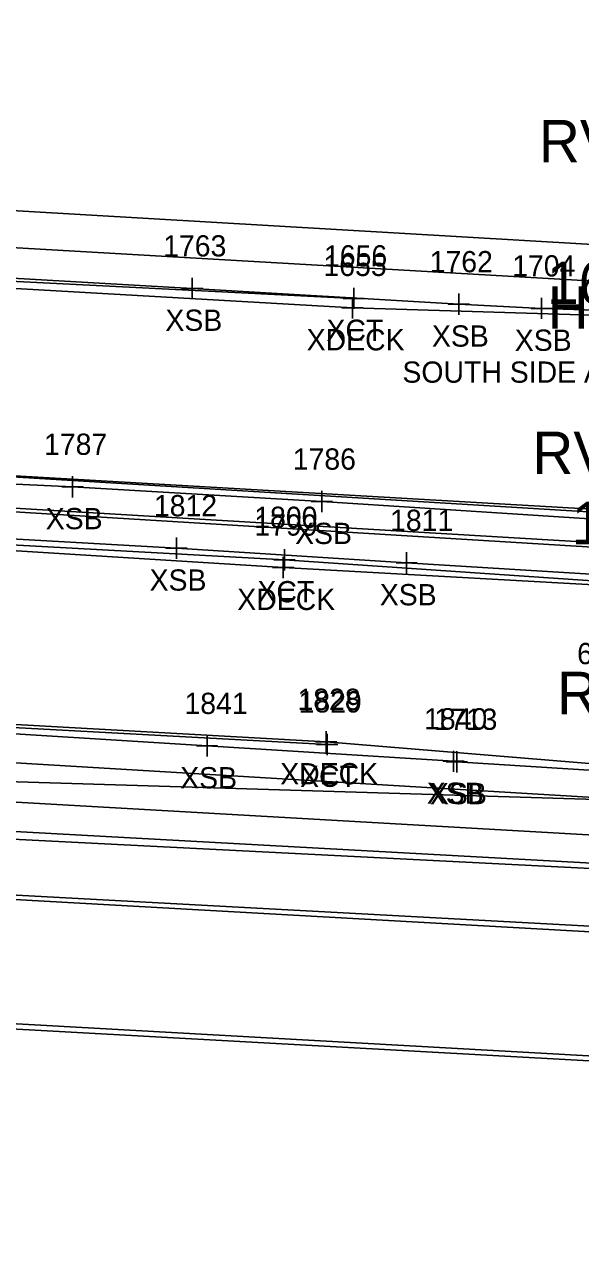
# Model space of a CAD drawing. Extents: x 1461855 to 1464118, y 556196 to 557441.
# Drawn here: x 1462290.7 to 1462316.9, y 556394.7 to 556452.7 of the extents above; entities that cross this region are included whole.
import ezdxf

# ---------------------------------------------------------------- set-up
doc = ezdxf.new("R2010")
doc.units = 0
for name, color, linetype in [('B_A', 7, 'Continuous'), ('B_C', 7, 'Continuous'), ('B_I', 7, 'Continuous'), ('B_TIC', 7, 'Continuous'), ('BB', 7, 'Continuous'), ('BDC', 7, 'Continuous'), ('BDEFAULT', 7, 'Continuous'), ('BELB', 7, 'Continuous'), ('BR', 7, 'Continuous'), ('C_A', 7, 'Continuous'), ('L_A', 7, 'Continuous'), ('L_I', 7, 'Continuous'), ('LSOGP', 7, 'Continuous'), ('UW', 7, 'Continuous')]:
    doc.layers.add(name, color=color, linetype=linetype)

msp = doc.modelspace()

# ---------------------------------------------------------------- linework, layer by layer
at = {"layer": 'B_TIC'}
for p, q in [((1462298.615, 556440.288), (1462298.691, 556440.288)), ((1462306.16, 556439.369), (1462306.236, 556439.369)), ((1462306.214, 556439.817), (1462306.289, 556439.817)), ((1462311.16, 556439.545), (1462311.236, 556439.545)), ((1462315.06, 556439.347), (1462315.135, 556439.347)), ((1462292.986, 556430.953), (1462293.061, 556430.953)), ((1462304.72, 556430.256), (1462304.795, 556430.256)), ((1462297.873, 556428.062), (1462297.949, 556428.062)), ((1462302.891, 556427.151), (1462302.967, 556427.151)), ((1462302.964, 556427.514), (1462303.039, 556427.514)), ((1462308.706, 556427.372), (1462308.782, 556427.372)), ((1462299.313, 556418.758), (1462299.388, 556418.758)), ((1462304.914, 556418.948), (1462304.989, 556418.948)), ((1462304.97, 556418.828), (1462305.046, 556418.828)), ((1462310.916, 556418.032), (1462310.992, 556418.032)), ((1462311.066, 556418.012), (1462311.141, 556418.012))]:
    msp.add_line(p, q, dxfattribs=at)
for points in [[(1462298.612, 556439.788), (1462298.612, 556440.788)], [(1462298.112, 556440.288), (1462299.112, 556440.288)], [(1462306.157, 556438.869), (1462306.157, 556439.869)], [(1462306.21, 556439.317), (1462306.21, 556440.317)], [(1462311.157, 556439.045), (1462311.157, 556440.045)], [(1462305.657, 556439.369), (1462306.657, 556439.369)], [(1462305.71, 556439.817), (1462306.71, 556439.817)], [(1462310.657, 556439.545), (1462311.657, 556439.545)], [(1462314.556, 556439.347), (1462315.556, 556439.347)], [(1462315.056, 556438.847), (1462315.056, 556439.847)], [(1462292.982, 556430.453), (1462292.982, 556431.453)], [(1462292.482, 556430.953), (1462293.482, 556430.953)], [(1462304.716, 556429.756), (1462304.716, 556430.756)], [(1462304.216, 556430.256), (1462305.216, 556430.256)], [(1462297.87, 556427.562), (1462297.87, 556428.562)], [(1462297.37, 556428.062), (1462298.37, 556428.062)], [(1462302.96, 556427.014), (1462302.96, 556428.014)], [(1462308.703, 556426.872), (1462308.703, 556427.872)], [(1462302.388, 556427.151), (1462303.388, 556427.151)], [(1462302.46, 556427.514), (1462303.46, 556427.514)], [(1462302.888, 556426.651), (1462302.888, 556427.651)], [(1462308.203, 556427.372), (1462309.203, 556427.372)], [(1462299.309, 556418.258), (1462299.309, 556419.258)], [(1462304.91, 556418.448), (1462304.91, 556419.448)], [(1462304.967, 556418.328), (1462304.967, 556419.328)], [(1462298.809, 556418.758), (1462299.809, 556418.758)], [(1462304.41, 556418.948), (1462305.41, 556418.948)], [(1462304.467, 556418.828), (1462305.467, 556418.828)], [(1462310.913, 556417.532), (1462310.913, 556418.532)], [(1462311.062, 556417.512), (1462311.062, 556418.512)], [(1462310.413, 556418.032), (1462311.413, 556418.032)], [(1462310.562, 556418.012), (1462311.562, 556418.012)]]:
    msp.add_lwpolyline(points, dxfattribs=at)
at = {"layer": 'BB'}
for points in [[(1462330.314, 556439.882), (1462152.032, 556450.172)], [(1462330.281, 556438.56), (1462322.158, 556439.115), (1462315.056, 556439.347), (1462311.157, 556439.545), (1462298.612, 556440.288), (1462285.489, 556441.028), (1462275.964, 556441.553), (1462262.291, 556442.26), (1462250.561, 556442.934), (1462239.101, 556443.725), (1462221.451, 556445.028), (1462206.294, 556446.009), (1462196.428, 556446.584), (1462185.17, 556447.223), (1462170.563, 556447.948), (1462158.846, 556448.597), (1462153.063, 556449.174)], [(1462328.781, 556428.634), (1462324.065, 556428.892), (1462319.456, 556429.171), (1462319.262, 556429.313), (1462304.716, 556430.256), (1462292.982, 556430.953), (1462284.287, 556431.363), (1462273.947, 556431.84), (1462261.623, 556432.561), (1462248.124, 556433.552), (1462226.107, 556434.532), (1462213.355, 556435.513), (1462200.264, 556436.133), (1462186.601, 556437.408), (1462174.891, 556438.04), (1462163.053, 556438.684), (1462157.864, 556438.972), (1462151.418, 556439.478)], [(1462329.779, 556427.349), (1462151.293, 556438.257)], [(1462328.685, 556426.103), (1462325.057, 556426.385), (1462319.713, 556426.698), (1462318.91, 556426.742), (1462308.703, 556427.372), (1462297.87, 556428.062), (1462287.86, 556428.625), (1462279.228, 556429.453), (1462266.621, 556430.191), (1462257.639, 556430.745), (1462248.392, 556431.143), (1462238.993, 556431.689), (1462230.236, 556432.512), (1462221.1, 556433.4), (1462212.022, 556433.761), (1462203.22, 556433.862), (1462192.615, 556434.352), (1462181.798, 556435.051), (1462171.497, 556435.694), (1462163.387, 556436.205), (1462158.362, 556436.371), (1462151.163, 556436.853)], [(1462329.432, 556416.833), (1462323.508, 556417.23), (1462311.062, 556418.012), (1462310.913, 556418.032), (1462299.309, 556418.758), (1462286.726, 556419.548), (1462277.774, 556420.048), (1462264.748, 556420.883), (1462247.065, 556421.852), (1462234.884, 556422.524), (1462220.758, 556423.428), (1462206.908, 556424.316), (1462197.488, 556424.752), (1462189.82, 556425.214), (1462178.304, 556425.855), (1462168.167, 556426.338), (1462157.727, 556426.705), (1462150.543, 556427.374)], [(1462329.287, 556415.62), (1462150.452, 556426.331)]]:
    msp.add_lwpolyline(points, dxfattribs=at)
at = {"layer": 'BDC'}
for points in [[(1462306.21, 556439.817), (1462267.643, 556441.754), (1462231.479, 556443.795), (1462195.28, 556445.964), (1462174.6, 556447.094)], [(1462330.253, 556427.044), (1462330.307, 556427.885), (1462321.119, 556429.542), (1462284.961, 556431.731), (1462249.264, 556433.812), (1462199.694, 556436.845), (1462158.901, 556439.284), (1462149.578, 556438.742), (1462149.473, 556437.83)], [(1462330.253, 556427.044), (1462320.906, 556426.297), (1462302.96, 556427.514), (1462266.959, 556429.497), (1462221.647, 556432.248), (1462185.847, 556434.519), (1462158.743, 556436.243), (1462149.473, 556437.83)], [(1462304.967, 556418.828), (1462275.389, 556420.423), (1462239.223, 556422.53), (1462203.029, 556424.75), (1462173.597, 556426.538)]]:
    msp.add_lwpolyline(points, dxfattribs=at)
at = {"layer": 'BDEFAULT'}
for points in [[(1462340.791, 556440.982), (1462140.486, 556452.697)], [(1462339.926, 556427), (1462139.852, 556438.871)], [(1462339.234, 556413.311), (1462138.867, 556424.749)], [(1462328.804, 556412.4), (1462155.31, 556421.202)]]:
    msp.add_lwpolyline(points, dxfattribs=at)
at = {"layer": 'BELB'}
for points in [[(1462332.261, 556438.564), (1462306.157, 556439.369), (1462267.585, 556441.59), (1462231.402, 556443.714), (1462195.311, 556445.79), (1462174.59, 556446.765), (1462149.769, 556449.202)], [(1462330.387, 556427.996), (1462321.219, 556429.671), (1462285.084, 556431.77), (1462249.268, 556434.079), (1462199.778, 556436.979), (1462159.012, 556439.444), (1462149.101, 556439.166)], [(1462330.387, 556427.996), (1462330.292, 556426.802), (1462320.892, 556426.149), (1462302.888, 556427.151), (1462266.996, 556429.395), (1462221.723, 556432.192), (1462185.76, 556434.369), (1462158.715, 556435.82), (1462149.068, 556437.555)], [(1462331.212, 556416.788), (1462304.91, 556418.948), (1462275.378, 556420.599), (1462239.194, 556422.631), (1462203.113, 556424.823), (1462173.724, 556426.567), (1462149.901, 556428.267), (1462148.306, 556426.947)], [(1462337.183, 556408.895), (1462260.894, 556413.183), (1462204.489, 556416.212), (1462146.838, 556419.281)], [(1462336.881, 556403.082), (1462260.891, 556407.332), (1462205.408, 556410.17), (1462146.764, 556413.378)]]:
    msp.add_lwpolyline(points, dxfattribs=at)
at = {"layer": 'BR'}
for points in [[(1462338.998, 556414.351), (1462338.8, 556409.121), (1462204.423, 556416.373), (1462146.886, 556419.56), (1462146.979, 556424.973)], [(1462356.157, 556401.791), (1462336.856, 556402.851), (1462260.866, 556407.054), (1462205.402, 556409.871), (1462146.909, 556413.108), (1462126.732, 556414.71), (1462111.281, 556416.663), (1462102.284, 556418.456)]]:
    msp.add_lwpolyline(points, dxfattribs=at)
at = {"layer": 'LSOGP'}
msp.add_lwpolyline([(1462152.286, 556411.553), (1462201.558, 556420.694), (1462202.678, 556419.763), (1462203.798, 556418.832), (1462262.402, 556416.239), (1462263.085, 556416.638), (1462263.768, 556417.037), (1462264.45, 556417.436), (1462265.133, 556417.835), (1462322.28, 556416.088), (1462328.247, 556406.014), (1462332.388, 556400.161), (1462335.319, 556389.349), (1462336.388, 556385.542), (1462337.181, 556366.3), (1462343.781, 556341.464)], dxfattribs=at)
at = {"layer": 'UW'}
msp.add_lwpolyline([(1462337.589, 556410.109), (1462335.376, 556410.001), (1462332.293, 556412.43), (1462148.132, 556422.524)], dxfattribs=at)

# ---------------------------------------------------------------- texts
at = {"layer": 'B_A'}
for s, p in [('XSB', (1462297.348, 556438.288)), ('XCT', (1462304.931, 556437.817)), ('XDECK', (1462303.999, 556437.369)), ('XSB', (1462309.893, 556437.545)), ('XSB', (1462313.793, 556437.347)), ('XSB', (1462291.718, 556428.953)), ('XSB', (1462303.453, 556428.256)), ('XSB', (1462296.606, 556426.062)), ('XCT', (1462301.681, 556425.514)), ('XDECK', (1462300.731, 556425.151)), ('XSB', (1462307.439, 556425.372)), ('XDECK', (1462302.753, 556416.948)), ('XCT', (1462303.687, 556416.828)), ('XSB', (1462298.046, 556416.758)), ('XSB', (1462309.649, 556416.032)), ('XSB', (1462309.799, 556416.012))]:
    msp.add_text(s, height=1, dxfattribs=at).set_placement(p)
at = {"layer": 'B_C'}
for s, p in [('SOUTH SIDE ARCH', (1462308.505, 556435.847)), ('6"X1\'-9" SOUTH SIDE WOOD ARCH', (1462316.724, 556422.603))]:
    msp.add_text(s, height=1, dxfattribs=at).set_placement(p)
at = {"layer": 'B_I'}
for s, p in [('1763', (1462297.242, 556441.788)), ('1656', (1462304.813, 556441.317)), ('1655', (1462304.786, 556440.869)), ('1762', (1462309.787, 556441.045)), ('1704', (1462313.671, 556440.847)), ('1787', (1462291.636, 556432.453)), ('1786', (1462303.342, 556431.756)), ('1812', (1462296.807, 556429.562)), ('1800', (1462301.531, 556429.014)), ('1799', (1462301.538, 556428.651)), ('1811', (1462307.923, 556428.872)), ('1828', (1462303.564, 556420.448)), ('1829', (1462303.616, 556420.328)), ('1841', (1462298.246, 556420.258)), ('1840', (1462309.523, 556419.532)), ('1713', (1462309.999, 556419.512))]:
    msp.add_text(s, height=1, dxfattribs=at).set_placement(p)
at = {"layer": 'C_A'}
msp.add_text('HVCTRL', height=2, dxfattribs=at).set_placement((1462315.338, 556438.386))
at = {"layer": 'L_A'}
for p in [(1462314.926, 556446.215), (1462314.617, 556431.547), (1462315.784, 556420.247)]:
    msp.add_text('RVRL', height=2, dxfattribs=at).set_placement(p)
at = {"layer": 'L_I'}
for s, p in [('1698', (1462315.31, 556439.547)), ('1697', (1462316.477, 556428.247))]:
    msp.add_text(s, height=2, dxfattribs=at).set_placement(p)

doc.saveas('drawing.dxf')
